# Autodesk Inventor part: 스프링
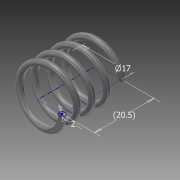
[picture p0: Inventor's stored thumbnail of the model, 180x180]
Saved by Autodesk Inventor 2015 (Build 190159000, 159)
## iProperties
Created: 2017-07
Part Number: 스프링
Material: 스테인레스 스틸
Document SubType Name: Modeling
Designer: owner
Density: 8 g/cm^3
Appearance: 반연마
Mass: 5.25801 g
Surface Area: 13.3788 cm^2
Volume: 0.657252 cm^3
Author: owner
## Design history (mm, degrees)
sketch "스케치1"
  geometry: L1 (0, 0)-(8.5, 0); L2 (8.5, 0)-(8.5, 20.5); L3 (8.5, 20.5)-(0, 20.5); L4 (0, 20.5)-(0, 0); C1 r 1 at (8.5, 0)
  constraints: 8 end point, 2 parallel, 1 centre point, 1 coincident, 1 horizontal, 1 perpendicular
  dimensions: "d0" = 20.5 distance of L2.end L1.end (derived); "d1" = 17 diameter of L2 L4; "d2" = 2 diameter of C1
feature "코일1" sketch "스케치1" pitch "d3" = 10; turns "d5" = 4; dims "d4" = 20.5 (= d0), "d6" = 0, angle "d7" = 90 deg, angle "d8" = 90 deg, "d9" = 0, "d10" = 0
sketch "스케치2"
  geometry: L1 (-9.5, 0)-(-7.5, 0) reference; 1 further point
  constraints: 1 horizontal alignment
extrude "돌출1" cut sketch "스케치2" stored distance "d11" = 10; taper "d12" = 0 deg
node "작업 평면1"
sketch "스케치3"
  geometry: L1 (1, 0)-(-1, 0) reference; 1 further point
  constraints: 1 horizontal alignment
extrude "돌출2" cut sketch "스케치3" stored distance "d14" = 10; taper "d15" = 0 deg
node "솔리드1"
node "절단 모서리 투영1"
node "절단 모서리 투영2"
other parameters: "d13" = 90 deg
